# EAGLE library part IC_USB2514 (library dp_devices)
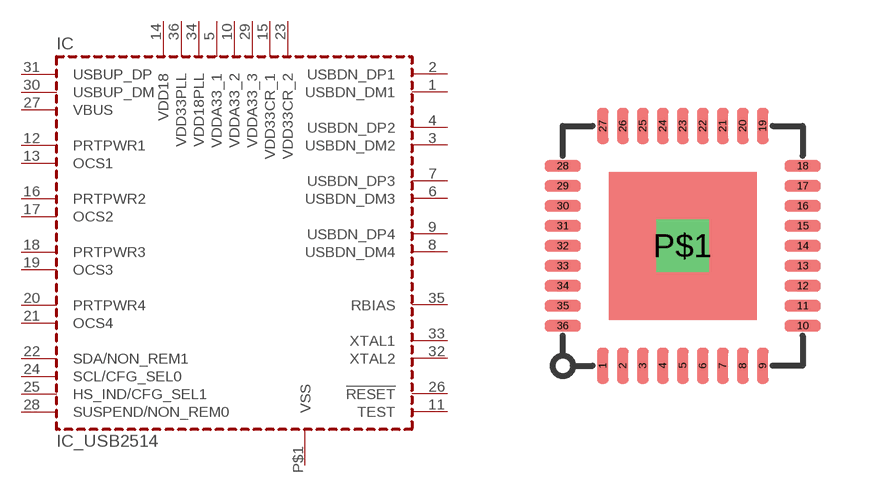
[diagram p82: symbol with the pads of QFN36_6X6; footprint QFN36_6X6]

Designator prefix IC

## IC_USB2514  [QFN36_6X6]
1  USBDN_DM1
2  USBDN_DP1
3  USBDN_DM2
4  USBDN_DP2
5  VDDA33_1
6  USBDN_DM3
7  USBDN_DP3
8  USBDN_DM4
9  USBDN_DP4
10  VDDA33_2
11  TEST
12  PRTPWR1
13  OCS1
14  VDD18
15  VDD33CR_1
16  PRTPWR2
17  OCS2
18  PRTPWR3
19  OCS3
20  PRTPWR4
21  OCS4
22  SDA/NON_REM1
23  VDD33CR_2
24  SCL/CFG_SEL0
25  HS_IND/CFG_SEL1
26  !RESET
27  VBUS
28  SUSPEND/NON_REM0
29  VDDA33_3
30  USBUP_DM
31  USBUP_DP
32  XTAL2
33  XTAL1
34  VDD18PLL
35  RBIAS
36  VDD33PLL
P$1  VSS

## Footprint QFN36_6X6 (pad centres in mm)
smd 0.28 x 0.9: 1 -2,-3; 2 -1.5,-3; 3 -1,-3; 4 -0.5,-3; 5 0,-3; 6 0.5,-3; 7 1,-3; 8 1.5,-3; 9 2,-3; 19 2,3; 20 1.5,3; 21 1,3; 22 0.5,3; 23 0,3; 24 -0.5,3; 25 -1,3; 26 -1.5,3; 27 -2,3
smd 0.9 x 0.28: 10 3,-2; 11 3,-1.5; 12 3,-1; 13 3,-0.5; 14 3,0; 15 3,0.5; 16 3,1; 17 3,1.5; 18 3,2; 28 -3,2; 29 -3,1.5; 30 -3,1; 31 -3,0.5; 32 -3,0; 33 -3,-0.5; 34 -3,-1; 35 -3,-1.5; 36 -3,-2
drill 0.8 square: P$1 0,0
